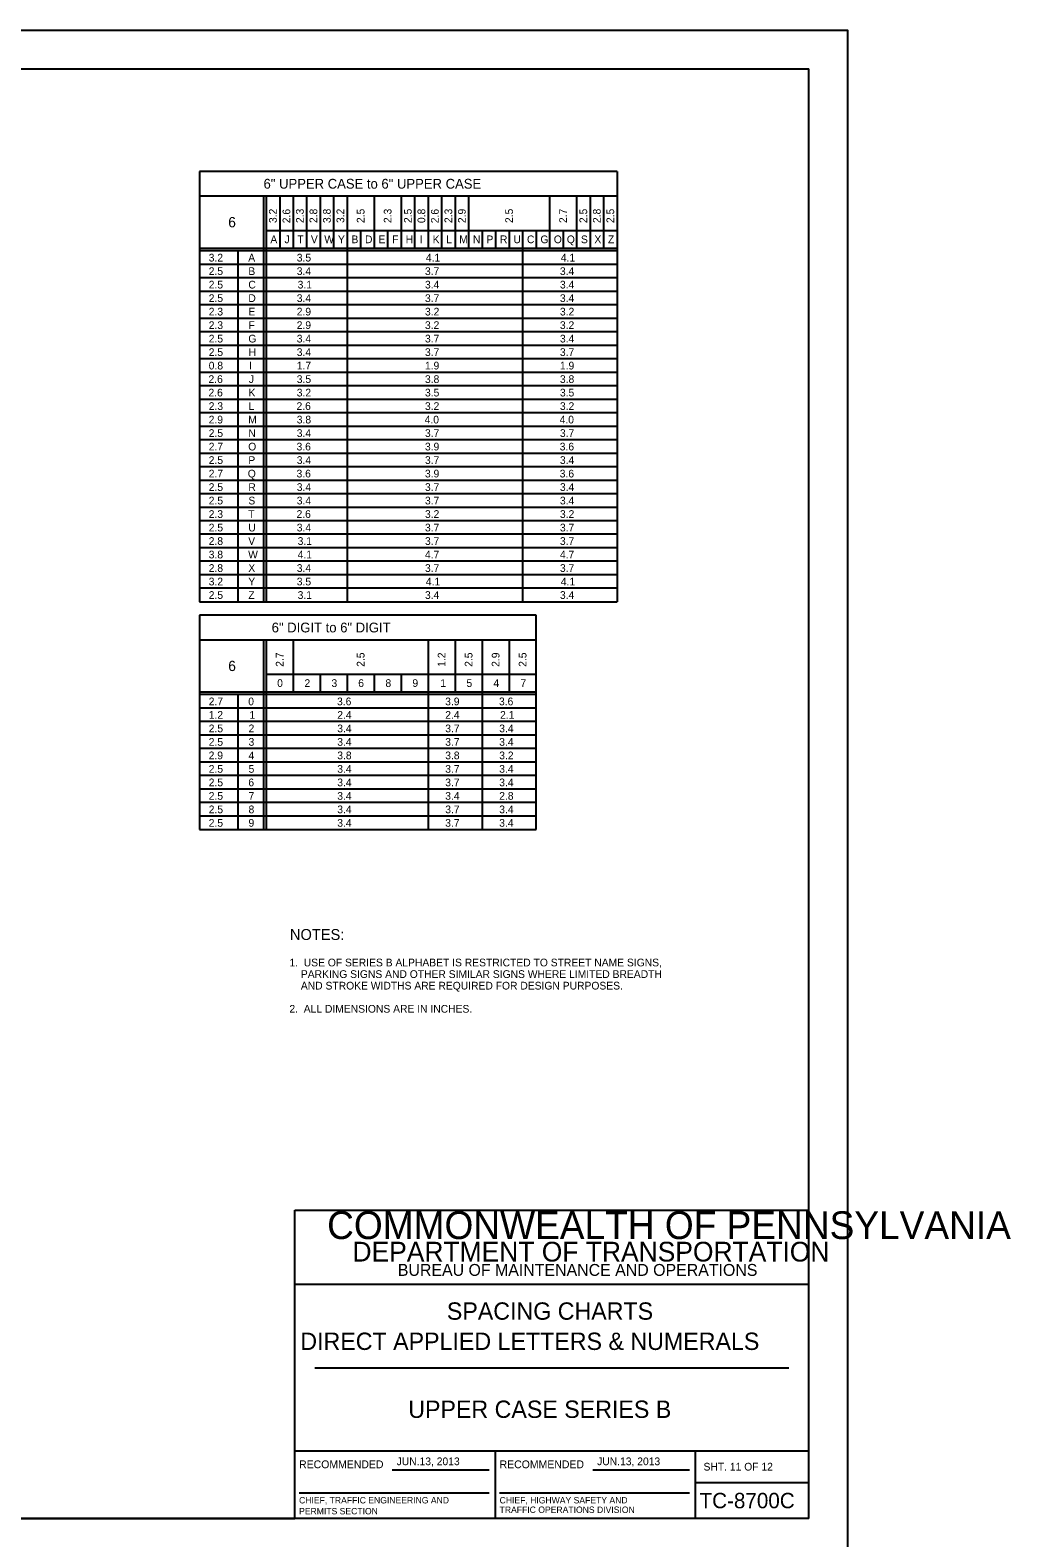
# Model space of a CAD drawing. Extents: x 638421 to 641849, y 297270 to 299646.
# Drawn here: x 641467 to 641849, y 299059 to 299646 of the extents above; entities that cross this region are included whole.
import ezdxf

# ---------------------------------------------------------------- set-up
doc = ezdxf.new("R2010")
doc.units = 0
for name, color, linetype in [('1', 7, 'Continuous'), ('2', 7, 'Continuous'), ('XCS-GRID-HVGL', 7, 'Continuous')]:
    doc.layers.add(name, color=color, linetype=linetype)

msp = doc.modelspace()

# ---------------------------------------------------------------- linework, layer by layer
at = {"layer": '1'}
for p, q in [((640984.31, 299630.63), (641770.31, 299630.63)), ((641770.31, 299066.63), (641770.31, 299630.63)), ((641570.31, 299066.63), (641570.31, 299186.63)), ((641570.31, 299186.63), (641770.31, 299186.63)), ((641770.31, 299157.63), (641570.31, 299157.63)), ((641578.06, 299125.31), (641762.56, 299125.31)), ((641570.31, 299093), (641770.31, 299093)), ((641648.31, 299093), (641648.31, 299066.63)), ((641726.19, 299066.63), (641726.19, 299093)), ((641608.24, 299085.57), (641645.87, 299085.57)), ((641686.24, 299085.57), (641723.87, 299085.57)), ((641726.19, 299080.63), (641770.31, 299080.63)), ((641571.99, 299076.68), (641645.87, 299076.68)), ((641649.99, 299076.68), (641723.87, 299076.68)), ((641770.31, 299066.63), (640984.31, 299066.63)), ((640984.31, 299066.63), (641570.31, 299066.63))]:
    msp.add_line(p, q, dxfattribs=at)
at = {"layer": '2'}
for p, q in [((641695.69, 299590.63), (641533.19, 299590.63)), ((641533.19, 299590.63), (641533.19, 299423.25)), ((641695.69, 299590.63), (641695.69, 299423.25)), ((641533.19, 299581.13), (641695.69, 299581.13)), ((641558.19, 299581.13), (641558.19, 299423.25)), ((641559.19, 299581.13), (641559.19, 299423.25)), ((641564.44, 299581.13), (641564.44, 299560.75)), ((641569.69, 299581.13), (641569.69, 299560.75)), ((641574.94, 299581.13), (641574.94, 299560.75)), ((641580.19, 299581.13), (641580.19, 299560.75)), ((641585.44, 299581.13), (641585.44, 299560.75)), ((641590.69, 299581.13), (641590.69, 299423.25)), ((641601.19, 299581.13), (641601.19, 299560.75)), ((641611.69, 299581.13), (641611.69, 299560.75)), ((641616.94, 299581.13), (641616.94, 299560.75)), ((641622.19, 299581.13), (641622.19, 299560.75)), ((641627.44, 299581.13), (641627.44, 299560.75)), ((641632.69, 299581.13), (641632.69, 299560.75)), ((641637.94, 299581.13), (641637.94, 299560.75)), ((641669.44, 299581.13), (641669.44, 299560.75)), ((641679.94, 299581.13), (641679.94, 299560.75)), ((641685.19, 299581.13), (641685.19, 299560.75)), ((641690.44, 299581.13), (641690.44, 299560.75)), ((641559.19, 299567.75), (641695.69, 299567.75)), ((641595.94, 299567.75), (641595.94, 299560.75)), ((641606.44, 299567.75), (641606.44, 299560.75)), ((641643.19, 299567.75), (641643.19, 299560.75)), ((641648.44, 299567.75), (641648.44, 299560.75)), ((641653.69, 299567.75), (641653.69, 299560.75)), ((641653.69, 299567.75), (641653.69, 299560.75)), ((641658.94, 299567.75), (641658.94, 299423.25)), ((641664.19, 299567.75), (641664.19, 299560.75)), ((641674.69, 299567.75), (641674.69, 299560.75)), ((641695.69, 299560.75), (641533.19, 299560.75)), ((641695.69, 299559.75), (641533.19, 299559.75)), ((641548.19, 299559.75), (641548.19, 299423.25)), ((641695.69, 299554.5), (641533.19, 299554.5)), ((641695.69, 299549.25), (641533.19, 299549.25)), ((641695.69, 299544), (641533.19, 299544)), ((641695.69, 299538.75), (641533.19, 299538.75)), ((641695.69, 299533.5), (641533.19, 299533.5)), ((641695.69, 299533.5), (641580.61, 299533.5)), ((641695.69, 299528.25), (641533.19, 299528.25)), ((641695.69, 299528.25), (641580.61, 299528.25)), ((641695.69, 299523), (641533.19, 299523)), ((641695.69, 299523), (641580.61, 299523)), ((641695.69, 299517.75), (641533.19, 299517.75)), ((641695.69, 299512.5), (641533.19, 299512.5)), ((641695.69, 299507.25), (641533.19, 299507.25)), ((641695.69, 299502), (641533.19, 299502)), ((641695.69, 299496.75), (641533.19, 299496.75)), ((641695.69, 299491.5), (641533.19, 299491.5)), ((641695.69, 299486.25), (641533.19, 299486.25)), ((641695.69, 299481), (641533.19, 299481)), ((641695.69, 299475.75), (641533.19, 299475.75)), ((641695.69, 299470.5), (641533.19, 299470.5)), ((641695.69, 299465.25), (641533.19, 299465.25)), ((641695.69, 299460), (641533.19, 299460)), ((641695.69, 299454.75), (641533.19, 299454.75)), ((641695.69, 299449.5), (641533.19, 299449.5)), ((641695.69, 299444.25), (641533.19, 299444.25)), ((641695.69, 299439), (641533.19, 299439)), ((641695.69, 299433.75), (641533.19, 299433.75)), ((641695.69, 299428.5), (641533.19, 299428.5)), ((641533.19, 299423.25), (641533.19, 299423.25)), ((641533.19, 299423.25), (641695.69, 299423.25)), ((641664.19, 299418), (641533.19, 299418)), ((641533.19, 299418), (641533.19, 299334.63)), ((641664.19, 299334.63), (641664.19, 299418)), ((641533.19, 299408.5), (641664.19, 299408.5)), ((641558.19, 299408.5), (641558.19, 299334.63)), ((641559.19, 299408.5), (641559.19, 299334.63)), ((641569.69, 299408.5), (641569.69, 299388.13)), ((641622.19, 299408.5), (641622.19, 299334.63)), ((641632.69, 299408.5), (641632.69, 299388.13)), ((641643.19, 299408.5), (641643.19, 299334.63)), ((641653.69, 299408.5), (641653.69, 299388.13)), ((641559.19, 299395.13), (641664.19, 299395.13)), ((641580.19, 299395.13), (641580.19, 299388.13)), ((641590.69, 299395.13), (641590.69, 299388.13)), ((641601.19, 299395.13), (641601.19, 299388.13)), ((641611.69, 299395.13), (641611.69, 299388.13)), ((641664.19, 299388.13), (641533.19, 299388.13)), ((641664.19, 299387.13), (641533.19, 299387.13)), ((641548.19, 299387.13), (641548.19, 299334.63)), ((641664.19, 299381.88), (641533.19, 299381.88)), ((641664.19, 299376.63), (641533.19, 299376.63)), ((641664.19, 299371.38), (641533.19, 299371.38)), ((641664.19, 299366.13), (641533.19, 299366.13)), ((641664.19, 299360.88), (641533.19, 299360.88)), ((641664.19, 299355.63), (641533.19, 299355.63)), ((641664.19, 299350.38), (641533.19, 299350.38)), ((641664.19, 299345.13), (641533.19, 299345.13)), ((641664.19, 299339.88), (641533.19, 299339.88)), ((641533.19, 299334.63), (641664.19, 299334.63))]:
    msp.add_line(p, q, dxfattribs=at)
at = {"layer": 'XCS-GRID-HVGL'}
msp.add_lwpolyline([(640944.31, 299645.63), (641785.31, 299645.63), (641785.31, 299051.63), (640944.31, 299051.63)], close=True, dxfattribs=at)

# ---------------------------------------------------------------- texts
at = {"layer": '1'}
for s, height, p in [('COMMONWEALTH OF PENNSYLVANIA', 10.7828, (641582.9, 299175.36)), ('DEPARTMENT OF TRANSPORTATION', 7.6837, (641592.76, 299166.61)), ('BUREAU OF MAINTENANCE AND OPERATIONS', 4.6253, (641610.41, 299161.04)), ('SPACING CHARTS', 6.75, (641629.47, 299143.97)), ('DIRECT APPLIED LETTERS & NUMERALS', 6.75, (641572.47, 299132.22)), ('UPPER CASE SERIES B', 6.75, (641614.45, 299105.78)), ('RECOMMENDED', 3.048, (641571.99, 299086.2)), ('RECOMMENDED', 3.048, (641649.99, 299086.2)), ('SHT. 11 OF 12', 3, (641729.32, 299085.31)), ('CHIEF, TRAFFIC ENGINEERING AND', 2.5, (641571.99, 299072.51)), ('CHIEF, HIGHWAY SAFETY AND', 2.5, (641649.99, 299072.51)), ('TC-8700C', 6, (641727.77, 299070.63)), ('PERMITS SECTION', 2.5, (641571.99, 299068.26)), ('TRAFFIC OPERATIONS DIVISION', 2.5, (641649.99, 299068.81))]:
    msp.add_text(s, height=height, dxfattribs=at).set_placement(p)
at = {"layer": '2'}
for s, height, p in [('6" UPPER CASE to 6" UPPER CASE', 3.8, (641558.17, 299583.98)), ('6', 4, (641544.44, 299568.94)), ('A', 3, (641560.83, 299562.75)), ('J', 3, (641566.32, 299562.75)), ('T', 3, (641571.32, 299562.75)), ('V', 3, (641576.58, 299562.75)), ('W', 3, (641581.81, 299562.75)), ('Y', 3, (641587.12, 299562.75)), ('B', 3, (641592.38, 299562.75)), ('D', 3, (641597.63, 299562.75)), ('E', 3, (641602.89, 299562.75)), ('F', 3, (641608.2, 299562.75)), ('H', 3, (641613.46, 299562.75)), ('I', 3, (641618.88, 299562.75)), ('K', 3, (641623.96, 299562.75)), ('L', 3, (641629.21, 299562.75)), ('M', 3, (641634.31, 299562.75)), ('N', 3, (641639.63, 299562.75)), ('P', 3, (641644.88, 299562.75)), ('R', 3, (641650.13, 299562.75)), ('U', 3, (641655.37, 299562.75)), ('C', 3, (641660.63, 299562.75)), ('G', 3, (641665.88, 299562.75)), ('O', 3, (641671.08, 299562.75)), ('Q', 3, (641676.15, 299562.75)), ('S', 3, (641681.64, 299562.75)), ('X', 3, (641686.87, 299562.75)), ('Z', 3, (641692.13, 299562.75)), ('3.2', 3, (641536.84, 299555.63)), ('A', 3, (641552.21, 299555.63)), ('3.5', 3, (641571.09, 299555.63)), ('4.1', 3, (641621.3, 299555.63)), ('4.1', 3, (641673.8, 299555.63)), ('2.5', 3, (641536.84, 299550.38)), ('B', 3, (641552.25, 299550.38)), ('3.4', 3, (641571.09, 299550.38)), ('3.7', 3, (641620.96, 299550.38)), ('3.4', 3, (641673.46, 299550.38)), ('2.5', 3, (641536.84, 299545.13)), ('C', 3, (641552.25, 299545.13)), ('3.1', 3, (641571.43, 299545.13)), ('3.4', 3, (641620.96, 299545.13)), ('3.4', 3, (641673.46, 299545.13)), ('2.5', 3, (641536.84, 299539.88)), ('2.3', 3, (641536.84, 299534.63)), ('D', 3, (641552.25, 299539.88)), ('E', 3, (641552.27, 299534.63)), ('3.4', 3, (641571.09, 299539.88)), ('2.9', 3, (641571.07, 299534.63)), ('3.7', 3, (641620.96, 299539.88)), ('3.2', 3, (641620.96, 299534.63)), ('3.4', 3, (641673.46, 299539.88)), ('3.2', 3, (641673.46, 299534.63)), ('2.3', 3, (641536.84, 299529.38)), ('F', 3, (641552.32, 299529.38)), ('2.9', 3, (641571.07, 299529.38)), ('3.2', 3, (641620.96, 299529.38)), ('3.2', 3, (641673.46, 299529.38)), ('2.5', 3, (641536.84, 299524.13)), ('G', 3, (641552.25, 299524.13)), ('3.4', 3, (641571.09, 299524.13)), ('3.7', 3, (641620.96, 299524.13)), ('3.4', 3, (641673.46, 299524.13)), ('2.5', 3, (641536.84, 299518.88)), ('H', 3, (641552.34, 299518.88)), ('3.4', 3, (641571.09, 299518.88)), ('3.7', 3, (641620.96, 299518.88)), ('3.7', 3, (641673.46, 299518.88)), ('0.8', 3, (641536.84, 299513.63)), ('I', 3, (641552.5, 299513.63)), ('1.7', 3, (641571.09, 299513.63)), ('1.9', 3, (641620.95, 299513.63)), ('1.9', 3, (641673.45, 299513.63)), ('2.6', 3, (641536.75, 299508.38)), ('J', 3, (641552.44, 299508.38)), ('3.5', 3, (641571.09, 299508.38)), ('3.8', 3, (641620.96, 299508.38)), ('3.8', 3, (641673.46, 299508.38)), ('2.6', 3, (641536.75, 299503.13)), ('K', 3, (641552.34, 299503.13)), ('3.2', 3, (641571.09, 299503.13)), ('3.5', 3, (641620.96, 299503.13)), ('3.5', 3, (641673.46, 299503.13)), ('2.3', 3, (641536.84, 299497.88)), ('L', 3, (641552.34, 299497.88)), ('2.6', 3, (641571, 299497.88)), ('3.2', 3, (641620.96, 299497.88)), ('3.2', 3, (641673.46, 299497.88)), ('2.9', 3, (641536.82, 299492.63)), ('2.5', 3, (641536.84, 299487.38)), ('M', 3, (641552.18, 299492.63)), ('N', 3, (641552.25, 299487.38)), ('3.8', 3, (641571.09, 299492.63)), ('3.4', 3, (641571.09, 299487.38)), ('4.0', 3, (641620.83, 299492.63)), ('3.7', 3, (641620.96, 299487.38)), ('4.0', 3, (641673.33, 299492.63)), ('3.7', 3, (641673.46, 299487.38)), ('2.7', 3, (641536.84, 299482.13)), ('O', 3, (641552.21, 299482.13)), ('3.6', 3, (641571, 299482.13)), ('3.9', 3, (641620.95, 299482.13)), ('3.6', 3, (641673.38, 299482.13)), ('2.5', 3, (641536.84, 299476.88)), ('P', 3, (641552.25, 299476.88)), ('3.4', 3, (641571.09, 299476.88)), ('3.7', 3, (641620.96, 299476.88)), ('3.4', 3, (641673.46, 299476.88)), ('2.7', 3, (641536.84, 299471.63)), ('Q', 3, (641552.03, 299471.63)), ('3.6', 3, (641571, 299471.63)), ('3.9', 3, (641620.95, 299471.63)), ('3.6', 3, (641673.38, 299471.63)), ('2.5', 3, (641536.84, 299466.38)), ('R', 3, (641552.25, 299466.38)), ('3.4', 3, (641571.09, 299466.38)), ('3.7', 3, (641620.96, 299466.38)), ('3.4', 3, (641673.46, 299466.38)), ('2.5', 3, (641536.84, 299461.13)), ('S', 3, (641552.27, 299461.13)), ('3.4', 3, (641571.09, 299461.13)), ('3.7', 3, (641620.96, 299461.13)), ('3.4', 3, (641673.46, 299461.13)), ('2.3', 3, (641536.84, 299455.88)), ('T', 3, (641552.19, 299455.88)), ('2.6', 3, (641571, 299455.88)), ('3.2', 3, (641620.96, 299455.88)), ('3.2', 3, (641673.46, 299455.88)), ('2.5', 3, (641536.84, 299450.63)), ('U', 3, (641552.24, 299450.63)), ('3.4', 3, (641571.09, 299450.63)), ('3.7', 3, (641620.96, 299450.63)), ('3.7', 3, (641673.46, 299450.63)), ('2.8', 3, (641536.84, 299445.38)), ('V', 3, (641552.21, 299445.38)), ('3.1', 3, (641571.43, 299445.38)), ('3.7', 3, (641620.96, 299445.38)), ('3.7', 3, (641673.46, 299445.38)), ('3.8', 3, (641536.84, 299440.13)), ('2.8', 3, (641536.84, 299434.88)), ('W', 3, (641552.18, 299440.13)), ('X', 3, (641552.24, 299434.88)), ('3.4', 3, (641571.09, 299434.88)), ('4.1', 3, (641571.43, 299440.13)), ('4.7', 3, (641620.96, 299440.13)), ('3.7', 3, (641620.96, 299434.88)), ('4.7', 3, (641673.46, 299440.13)), ('3.7', 3, (641673.46, 299434.88)), ('3.2', 3, (641536.84, 299429.63)), ('Y', 3, (641552.24, 299429.63)), ('3.5', 3, (641571.09, 299429.63)), ('4.1', 3, (641621.3, 299429.63)), ('4.1', 3, (641673.8, 299429.63)), ('2.5', 3, (641536.84, 299424.38)), ('Z', 3, (641552.25, 299424.38)), ('3.1', 3, (641571.43, 299424.38)), ('3.4', 3, (641620.96, 299424.38)), ('3.4', 3, (641673.46, 299424.38)), ('6" DIGIT to 6" DIGIT', 3.8, (641561.33, 299411.35)), ('6', 4, (641544.44, 299396.31)), ('0', 3, (641563.46, 299390.13)), ('2', 3, (641574.09, 299390.13)), ('3', 3, (641584.59, 299390.13)), ('6', 3, (641595, 299390.13)), ('8', 3, (641605.59, 299390.13)), ('9', 3, (641616.07, 299390.13)), ('1', 3, (641626.93, 299390.13)), ('5', 3, (641637.09, 299390.13)), ('4', 3, (641647.59, 299390.13)), ('7', 3, (641658.09, 299390.13)), ('2.7', 3, (641536.84, 299383)), ('0', 3, (641552.21, 299383)), ('3.6', 3, (641586.75, 299383)), ('3.9', 3, (641628.82, 299383)), ('3.6', 3, (641649.75, 299383)), ('1.2', 3, (641536.84, 299377.75)), ('1', 3, (641552.68, 299377.75)), ('2.4', 3, (641586.84, 299377.75)), ('2.4', 3, (641628.84, 299377.75)), ('2.1', 3, (641650.18, 299377.75)), ('2.5', 3, (641536.84, 299372.5)), ('2', 3, (641552.34, 299372.5)), ('3.4', 3, (641586.84, 299372.5)), ('3.7', 3, (641628.84, 299372.5)), ('3.4', 3, (641649.84, 299372.5)), ('2.5', 3, (641536.84, 299367.25)), ('3', 3, (641552.34, 299367.25)), ('3.4', 3, (641586.84, 299367.25)), ('3.7', 3, (641628.84, 299367.25)), ('3.4', 3, (641649.84, 299367.25)), ('2.9', 3, (641536.82, 299362)), ('4', 3, (641552.34, 299362)), ('3.8', 3, (641586.84, 299362)), ('3.8', 3, (641628.84, 299362)), ('3.2', 3, (641649.84, 299362)), ('2.5', 3, (641536.84, 299356.75)), ('5', 3, (641552.34, 299356.75)), ('3.4', 3, (641586.84, 299356.75)), ('3.7', 3, (641628.84, 299356.75)), ('3.4', 3, (641649.84, 299356.75)), ('2.5', 3, (641536.84, 299351.5)), ('6', 3, (641552.25, 299351.5)), ('3.4', 3, (641586.84, 299351.5)), ('3.7', 3, (641628.84, 299351.5)), ('3.4', 3, (641649.84, 299351.5)), ('2.5', 3, (641536.84, 299346.25)), ('2.5', 3, (641536.84, 299341)), ('8', 3, (641552.34, 299341)), ('7', 3, (641552.34, 299346.25)), ('3.4', 3, (641586.84, 299346.25)), ('3.4', 3, (641586.84, 299341)), ('3.4', 3, (641628.84, 299346.25)), ('3.7', 3, (641628.84, 299341)), ('3.4', 3, (641649.84, 299341)), ('2.8', 3, (641649.84, 299346.25)), ('2.5', 3, (641536.84, 299335.75)), ('9', 3, (641552.32, 299335.75)), ('3.4', 3, (641586.84, 299335.75)), ('3.7', 3, (641628.84, 299335.75)), ('3.4', 3, (641649.84, 299335.75)), ('NOTES:', 4.25, (641568.44, 299291.7)), ('1.  USE OF SERIES B ALPHABET IS RESTRICTED TO STREET NAME SIGNS,', 3, (641568.23, 299281.43)), ('    PARKING SIGNS AND OTHER SIMILAR SIGNS WHERE LIMITED BREADTH', 3, (641568.23, 299276.93)), ('    AND STROKE WIDTHS ARE REQUIRED FOR DESIGN PURPOSES.', 3, (641568.23, 299272.43)), ('2.  ALL DIMENSIONS ARE IN INCHES.', 3, (641568.23, 299263.43)), ('JUN.13, 2013', 3, (641609.93, 299087.39)), ('JUN.13, 2013', 3, (641687.93, 299087.39))]:
    msp.add_text(s, height=height, dxfattribs=at).set_placement(p)
for s, p in [('3.2', (641563.31, 299570.59)), ('2.6', (641568.56, 299570.51)), ('2.3', (641573.81, 299570.59)), ('2.8', (641579.06, 299570.59)), ('3.8', (641584.31, 299570.59)), ('3.2', (641589.56, 299570.59)), ('2.5', (641597.44, 299570.59)), ('2.3', (641607.94, 299570.59)), ('2.5', (641615.81, 299570.59)), ('0.8', (641621.06, 299570.59)), ('2.6', (641626.31, 299570.51)), ('2.3', (641631.56, 299570.59)), ('2.9', (641636.81, 299570.58)), ('2.5', (641655.19, 299570.59)), ('2.7', (641676.19, 299570.59)), ('2.5', (641684.06, 299570.59)), ('2.8', (641689.31, 299570.59)), ('2.5', (641694.56, 299570.59)), ('2.7', (641565.94, 299397.96)), ('2.5', (641597.44, 299397.96)), ('1.2', (641628.94, 299397.96)), ('2.5', (641639.44, 299397.96)), ('2.9', (641649.94, 299397.95)), ('2.5', (641660.44, 299397.96))]:
    msp.add_text(s, height=3, rotation=90, dxfattribs=at).set_placement(p)

doc.saveas('drawing.dxf')
